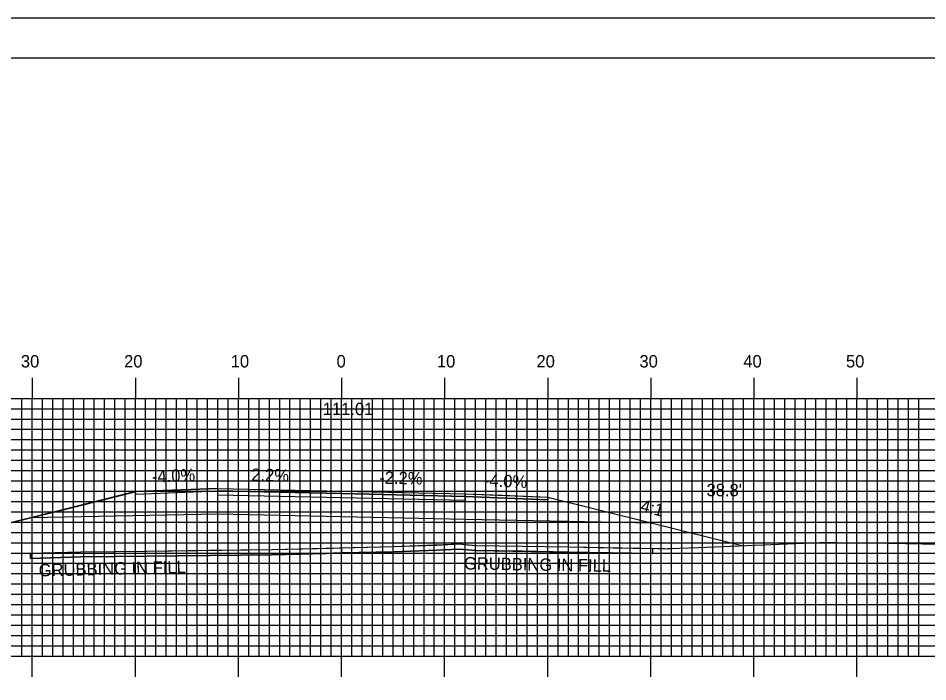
# Model space of a CAD drawing. Extents: x 1765726 to 1766069, y 442591 to 442811.
# Drawn here: x 1765860.5 to 1765948.8, y 442746.2 to 442810.5 of the extents above; entities that cross this region are included whole.
import ezdxf

# ---------------------------------------------------------------- set-up
doc = ezdxf.new("R2010")
doc.units = 0
for name, color, linetype in [('ANNOTATION', 7, 'Continuous'), ('BORDER', 7, 'Continuous'), ('D_Roadway_Centerline', 7, 'Continuous'), ('D_Roadway_Centerline_Text', 7, 'Continuous'), ('D_Roadway_Edge_Shoulder', 7, 'Continuous'), ('D_Roadway_Edge_TW', 7, 'Continuous'), ('D_Roadway_Pavement', 7, 'Continuous'), ('D_Roadway_SlopeLines', 7, 'Continuous'), ('D_Roadway_SubGrade', 7, 'Continuous'), ('D_Text_Standard', 7, 'Continuous'), ('GRUBBING IN FILL', 7, 'Continuous'), ('H_V ANNOTATION', 7, 'Continuous'), ('MAJOR', 7, 'Continuous'), ('MINOR', 7, 'Continuous'), ('PLOT BOUNDARY', 7, 'Continuous'), ('S_Roadway_Centerline', 7, 'Continuous')]:
    doc.layers.add(name, color=color, linetype=linetype)

msp = doc.modelspace()

# ---------------------------------------------------------------- linework, layer by layer
at = {"layer": 'BORDER'}
msp.add_lwpolyline([(1765742.284, 442596.665), (1766062.284, 442596.665), (1766062.284, 442806.665), (1765742.284, 442806.665)], close=True, dxfattribs=at)
at = {"layer": 'D_Roadway_Centerline'}
msp.add_lwpolyline([(1765846.219, 442758.202), (1765848.67, 442758.815), (1765859.877, 442761.616), (1765859.884, 442761.618), (1765861.71, 442762.075), (1765861.714, 442762.076), (1765864.219, 442762.702), (1765871.88, 442764.617), (1765871.884, 442764.618), (1765871.888, 442764.618), (1765879.884, 442764.938), (1765890.419, 442764.706), (1765891.884, 442764.674), (1765891.885, 442764.674), (1765903.884, 442764.41), (1765903.891, 442764.41), (1765907.462, 442764.267), (1765911.884, 442764.09), (1765922.058, 442761.547), (1765930.706, 442759.385), (1765930.709, 442759.384)], dxfattribs=at)
at = {"layer": 'D_Roadway_Edge_Shoulder'}
for points in [[(1765879.884, 442764.938), (1765871.884, 442764.618), (1765871.884, 442764.368), (1765879.884, 442764.688)], [(1765903.884, 442764.41), (1765911.884, 442764.09), (1765911.884, 442763.84), (1765903.884, 442764.16)]]:
    msp.add_lwpolyline(points, close=True, dxfattribs=at)
at = {"layer": 'D_Roadway_Edge_TW'}
msp.add_lwpolyline([(1765879.884, 442764.688), (1765879.884, 442764.938), (1765891.884, 442764.674), (1765903.884, 442764.41), (1765903.884, 442764.16), (1765891.884, 442764.424)], close=True, dxfattribs=at)
at = {"layer": 'D_Roadway_Pavement'}
msp.add_lwpolyline([(1765879.884, 442764.272), (1765879.884, 442764.688), (1765891.884, 442764.424), (1765903.884, 442764.16), (1765903.884, 442763.744), (1765891.884, 442764.008)], close=True, dxfattribs=at)
at = {"layer": 'D_Roadway_SlopeLines'}
for points in [[(1765871.884, 442764.618), (1765861.71, 442762.075), (1765859.884, 442761.618), (1765846.219, 442758.202)], [(1765911.884, 442764.09), (1765922.058, 442761.547), (1765930.709, 442759.384)]]:
    msp.add_lwpolyline(points, dxfattribs=at)
at = {"layer": 'D_Roadway_SubGrade'}
msp.add_lwpolyline([(1765879.884, 442762.438), (1765861.71, 442762.075), (1765871.884, 442764.618), (1765871.884, 442764.368), (1765879.884, 442764.688), (1765891.884, 442764.424), (1765903.884, 442764.16), (1765911.884, 442763.84), (1765911.884, 442764.09), (1765922.058, 442761.547), (1765903.884, 442761.91), (1765891.884, 442762.174)], close=True, dxfattribs=at)
at = {"layer": 'GRUBBING IN FILL'}
for p, q in [((1765861.71, 442758.647), (1765861.71, 442758.147)), ((1765922.058, 442759.112), (1765922.058, 442758.612))]:
    msp.add_line(p, q, dxfattribs=at)
for points in [[(1765861.71, 442758.147), (1765861.71, 442758.647), (1765863.444, 442758.697), (1765866.571, 442758.788), (1765869.789, 442758.822), (1765873.006, 442758.855), (1765879.079, 442758.93), (1765885.152, 442759.005), (1765891.032, 442759.15), (1765891.884, 442759.172), (1765891.884, 442758.671), (1765891.043, 442758.651), (1765885.161, 442758.505), (1765879.087, 442758.43), (1765873.012, 442758.355), (1765866.581, 442758.288)], [(1765861.71, 442758.147), (1765861.71, 442758.647), (1765863.444, 442758.697), (1765866.571, 442758.788), (1765869.789, 442758.822), (1765873.006, 442758.855), (1765879.079, 442758.93), (1765885.152, 442759.005), (1765891.032, 442759.15), (1765891.884, 442759.172), (1765891.884, 442758.671), (1765891.043, 442758.651), (1765885.161, 442758.505), (1765879.087, 442758.43), (1765873.012, 442758.355), (1765866.581, 442758.288)], [(1765891.884, 442759.172), (1765896.911, 442759.296), (1765903.333, 442759.541), (1765904.127, 442759.475), (1765904.922, 442759.409), (1765909.411, 442759.33), (1765913.899, 442759.251), (1765918.225, 442759.177), (1765922.058, 442759.112), (1765922.058, 442758.612), (1765917.974, 442758.682), (1765913.89, 442758.751), (1765909.394, 442758.83), (1765904.897, 442758.909), (1765904.11, 442758.975), (1765903.324, 442759.04), (1765901.117, 442758.932), (1765896.925, 442758.796), (1765891.884, 442758.671)], [(1765891.884, 442759.172), (1765896.911, 442759.296), (1765903.333, 442759.541), (1765904.127, 442759.475), (1765904.922, 442759.409), (1765909.411, 442759.33), (1765913.899, 442759.251), (1765918.225, 442759.177), (1765922.058, 442759.112), (1765922.058, 442758.612), (1765917.974, 442758.682), (1765913.89, 442758.751), (1765909.394, 442758.83), (1765904.897, 442758.909), (1765904.11, 442758.975), (1765903.324, 442759.04), (1765901.117, 442758.932), (1765896.925, 442758.796), (1765891.884, 442758.671)]]:
    msp.add_lwpolyline(points, close=True, dxfattribs=at)
msp.add_lwpolyline([(1765861.71, 442758.147), (1765866.581, 442758.288), (1765873.012, 442758.355), (1765885.161, 442758.505), (1765896.925, 442758.796), (1765901.117, 442758.932), (1765903.324, 442759.04), (1765904.897, 442758.909), (1765913.89, 442758.751), (1765922.058, 442758.612)], dxfattribs=at)
at = {"layer": 'MAJOR'}
for p, q in [((1765861.884, 442775.669), (1765861.884, 442773.665)), ((1765871.884, 442775.669), (1765871.884, 442773.665)), ((1765881.884, 442775.669), (1765881.884, 442773.665)), ((1765891.884, 442775.669), (1765891.884, 442773.665)), ((1765901.884, 442775.669), (1765901.884, 442773.665)), ((1765911.884, 442775.669), (1765911.884, 442773.665)), ((1765921.884, 442775.669), (1765921.884, 442773.665)), ((1765931.884, 442775.669), (1765931.884, 442773.665)), ((1765941.884, 442775.669), (1765941.884, 442773.665)), ((1765751.884, 442773.665), (1766031.884, 442773.665)), ((1765751.884, 442773.665), (1766031.884, 442773.665)), ((1765861.884, 442748.665), (1765861.884, 442773.665)), ((1765871.884, 442748.665), (1765871.884, 442773.665)), ((1765881.884, 442748.665), (1765881.884, 442773.665)), ((1765891.884, 442748.665), (1765891.884, 442773.665)), ((1765901.884, 442748.665), (1765901.884, 442773.665)), ((1765911.884, 442748.665), (1765911.884, 442773.665)), ((1765921.884, 442748.665), (1765921.884, 442773.665)), ((1765931.884, 442748.665), (1765931.884, 442773.665)), ((1765941.884, 442748.665), (1765941.884, 442773.665)), ((1765751.884, 442768.665), (1766031.884, 442768.665)), ((1765751.884, 442763.665), (1766031.884, 442763.665)), ((1765751.884, 442758.665), (1766031.884, 442758.665)), ((1765751.884, 442753.665), (1766031.884, 442753.665)), ((1765751.884, 442748.665), (1766031.884, 442748.665)), ((1765751.884, 442748.665), (1766031.884, 442748.665)), ((1765861.884, 442746.661), (1765861.884, 442748.665)), ((1765871.884, 442746.661), (1765871.884, 442748.665)), ((1765881.884, 442746.661), (1765881.884, 442748.665)), ((1765891.884, 442746.661), (1765891.884, 442748.665)), ((1765901.884, 442746.661), (1765901.884, 442748.665)), ((1765911.884, 442746.661), (1765911.884, 442748.665)), ((1765921.884, 442746.661), (1765921.884, 442748.665)), ((1765931.884, 442746.661), (1765931.884, 442748.665)), ((1765941.884, 442746.661), (1765941.884, 442748.665))]:
    msp.add_line(p, q, dxfattribs=at)
at = {"layer": 'MINOR'}
for p, q in [((1765860.884, 442748.665), (1765860.884, 442773.665)), ((1765862.884, 442748.665), (1765862.884, 442773.665)), ((1765863.884, 442748.665), (1765863.884, 442773.665)), ((1765864.884, 442748.665), (1765864.884, 442773.665)), ((1765865.884, 442748.665), (1765865.884, 442773.665)), ((1765866.884, 442748.665), (1765866.884, 442773.665)), ((1765867.884, 442748.665), (1765867.884, 442773.665)), ((1765868.884, 442748.665), (1765868.884, 442773.665)), ((1765869.884, 442748.665), (1765869.884, 442773.665)), ((1765870.884, 442748.665), (1765870.884, 442773.665)), ((1765872.884, 442748.665), (1765872.884, 442773.665)), ((1765873.884, 442748.665), (1765873.884, 442773.665)), ((1765874.884, 442748.665), (1765874.884, 442773.665)), ((1765875.884, 442748.665), (1765875.884, 442773.665)), ((1765876.884, 442748.665), (1765876.884, 442773.665)), ((1765877.884, 442748.665), (1765877.884, 442773.665)), ((1765878.884, 442748.665), (1765878.884, 442773.665)), ((1765879.884, 442748.665), (1765879.884, 442773.665)), ((1765880.884, 442748.665), (1765880.884, 442773.665)), ((1765882.884, 442748.665), (1765882.884, 442773.665)), ((1765883.884, 442748.665), (1765883.884, 442773.665)), ((1765884.884, 442748.665), (1765884.884, 442773.665)), ((1765885.884, 442748.665), (1765885.884, 442773.665)), ((1765886.884, 442748.665), (1765886.884, 442773.665)), ((1765887.884, 442748.665), (1765887.884, 442773.665)), ((1765888.884, 442748.665), (1765888.884, 442773.665)), ((1765889.884, 442748.665), (1765889.884, 442773.665)), ((1765890.884, 442748.665), (1765890.884, 442773.665)), ((1765892.884, 442748.665), (1765892.884, 442773.665)), ((1765893.884, 442748.665), (1765893.884, 442773.665)), ((1765894.884, 442748.665), (1765894.884, 442773.665)), ((1765895.884, 442748.665), (1765895.884, 442773.665)), ((1765896.884, 442748.665), (1765896.884, 442773.665)), ((1765897.884, 442748.665), (1765897.884, 442773.665)), ((1765898.884, 442748.665), (1765898.884, 442773.665)), ((1765899.884, 442748.665), (1765899.884, 442773.665)), ((1765900.884, 442748.665), (1765900.884, 442773.665)), ((1765902.884, 442748.665), (1765902.884, 442773.665)), ((1765903.884, 442748.665), (1765903.884, 442773.665)), ((1765904.884, 442748.665), (1765904.884, 442773.665)), ((1765905.884, 442748.665), (1765905.884, 442773.665)), ((1765906.884, 442748.665), (1765906.884, 442773.665)), ((1765907.884, 442748.665), (1765907.884, 442773.665)), ((1765908.884, 442748.665), (1765908.884, 442773.665)), ((1765909.884, 442748.665), (1765909.884, 442773.665)), ((1765910.884, 442748.665), (1765910.884, 442773.665)), ((1765912.884, 442748.665), (1765912.884, 442773.665)), ((1765913.884, 442748.665), (1765913.884, 442773.665)), ((1765914.884, 442748.665), (1765914.884, 442773.665)), ((1765915.884, 442748.665), (1765915.884, 442773.665)), ((1765916.884, 442748.665), (1765916.884, 442773.665)), ((1765917.884, 442748.665), (1765917.884, 442773.665)), ((1765918.884, 442748.665), (1765918.884, 442773.665)), ((1765919.884, 442748.665), (1765919.884, 442773.665)), ((1765920.884, 442748.665), (1765920.884, 442773.665)), ((1765922.884, 442748.665), (1765922.884, 442773.665)), ((1765923.884, 442748.665), (1765923.884, 442773.665)), ((1765924.884, 442748.665), (1765924.884, 442773.665)), ((1765925.884, 442748.665), (1765925.884, 442773.665)), ((1765926.884, 442748.665), (1765926.884, 442773.665)), ((1765927.884, 442748.665), (1765927.884, 442773.665)), ((1765928.884, 442748.665), (1765928.884, 442773.665)), ((1765929.884, 442748.665), (1765929.884, 442773.665)), ((1765930.884, 442748.665), (1765930.884, 442773.665)), ((1765932.884, 442748.665), (1765932.884, 442773.665)), ((1765933.884, 442748.665), (1765933.884, 442773.665)), ((1765934.884, 442748.665), (1765934.884, 442773.665)), ((1765935.884, 442748.665), (1765935.884, 442773.665)), ((1765936.884, 442748.665), (1765936.884, 442773.665)), ((1765937.884, 442748.665), (1765937.884, 442773.665)), ((1765938.884, 442748.665), (1765938.884, 442773.665)), ((1765939.884, 442748.665), (1765939.884, 442773.665)), ((1765940.884, 442748.665), (1765940.884, 442773.665)), ((1765942.884, 442748.665), (1765942.884, 442773.665)), ((1765943.884, 442748.665), (1765943.884, 442773.665)), ((1765944.884, 442748.665), (1765944.884, 442773.665)), ((1765945.884, 442748.665), (1765945.884, 442773.665)), ((1765946.884, 442748.665), (1765946.884, 442773.665)), ((1765947.884, 442748.665), (1765947.884, 442773.665)), ((1765751.884, 442772.665), (1766031.884, 442772.665)), ((1765751.884, 442771.665), (1766031.884, 442771.665)), ((1765751.884, 442770.665), (1766031.884, 442770.665)), ((1765751.884, 442769.665), (1766031.884, 442769.665)), ((1765751.884, 442767.665), (1766031.884, 442767.665)), ((1765751.884, 442766.665), (1766031.884, 442766.665)), ((1765751.884, 442765.665), (1766031.884, 442765.665)), ((1765751.884, 442764.665), (1766031.884, 442764.665)), ((1765751.884, 442762.665), (1766031.884, 442762.665)), ((1765751.884, 442761.665), (1766031.884, 442761.665)), ((1765751.884, 442760.665), (1766031.884, 442760.665)), ((1765751.884, 442759.665), (1766031.884, 442759.665)), ((1765751.884, 442757.665), (1766031.884, 442757.665)), ((1765751.884, 442756.665), (1766031.884, 442756.665)), ((1765751.884, 442755.665), (1766031.884, 442755.665)), ((1765751.884, 442754.665), (1766031.884, 442754.665)), ((1765751.884, 442752.665), (1766031.884, 442752.665)), ((1765751.884, 442751.665), (1766031.884, 442751.665)), ((1765751.884, 442750.665), (1766031.884, 442750.665)), ((1765751.884, 442749.665), (1766031.884, 442749.665))]:
    msp.add_line(p, q, dxfattribs=at)
at = {"layer": 'PLOT BOUNDARY'}
msp.add_lwpolyline([(1765726.097, 442590.547), (1766066.097, 442590.547), (1766066.097, 442810.547), (1765726.097, 442810.547)], close=True, dxfattribs=at)
at = {"layer": 'S_Roadway_Centerline'}
msp.add_lwpolyline([(1765860.316, 442758.607), (1765866.571, 442758.788), (1765873.006, 442758.855), (1765885.152, 442759.005), (1765896.911, 442759.296), (1765901.097, 442759.431), (1765903.333, 442759.541), (1765904.922, 442759.409), (1765913.899, 442759.251), (1765922.55, 442759.104), (1765923.213, 442759.093), (1765923.488, 442759.086), (1765923.542, 442759.09), (1765923.754, 442759.099), (1765926.479, 442759.208), (1765938.292, 442759.701), (1765939.991, 442759.679), (1765944.957, 442759.62), (1765958.021, 442759.36)], dxfattribs=at)

# ---------------------------------------------------------------- texts
at = {"layer": 'ANNOTATION'}
for s, rotation, p in [('-4.0%', 2.29068, (1765873.518, 442765.485)), ('2.2%', 358.73968, (1765883.12, 442765.668)), ('-2.2%', 358.73968, (1765895.532, 442765.394)), ('-4.0%', 357.70946, (1765905.68, 442765.14)), ('4:1', 345.96406, (1765920.801, 442762.723))]:
    msp.add_text(s, height=1.2, rotation=rotation, dxfattribs=at).set_placement(p)
at = {"layer": 'D_Roadway_Centerline'}
for s, p in [('C', (1765891.879, 442764.674)), ('L', (1765891.884, 442764.667))]:
    msp.add_text(s, height=0.0146, dxfattribs=at).set_placement(p)
at = {"layer": 'D_Roadway_Centerline_Text'}
msp.add_text('111.01', height=1.2, dxfattribs=at).set_placement((1765890.065, 442772.043))
at = {"layer": 'D_Text_Standard'}
msp.add_text("38.8'", height=1.2, dxfattribs=at).set_placement((1765927.291, 442764.176))
at = {"layer": 'GRUBBING IN FILL'}
for rotation, p in [(359.02711, (1765903.752, 442757.077)), (1.34777, (1765862.526, 442756.389))]:
    msp.add_text('GRUBBING IN FILL', height=1.2, rotation=rotation, dxfattribs=at).set_placement(p)
at = {"layer": 'H_V ANNOTATION'}
for s, p in [('30', (1765860.781, 442776.665)), ('20', (1765870.792, 442776.665)), ('10', (1765881.135, 442776.665)), ('0', (1765891.402, 442776.665)), ('10', (1765901.135, 442776.665)), ('20', (1765910.792, 442776.665)), ('30', (1765920.781, 442776.665)), ('40', (1765930.856, 442776.665)), ('50', (1765940.813, 442776.665))]:
    msp.add_text(s, height=1.2, dxfattribs=at).set_placement(p)

doc.saveas('drawing.dxf')
